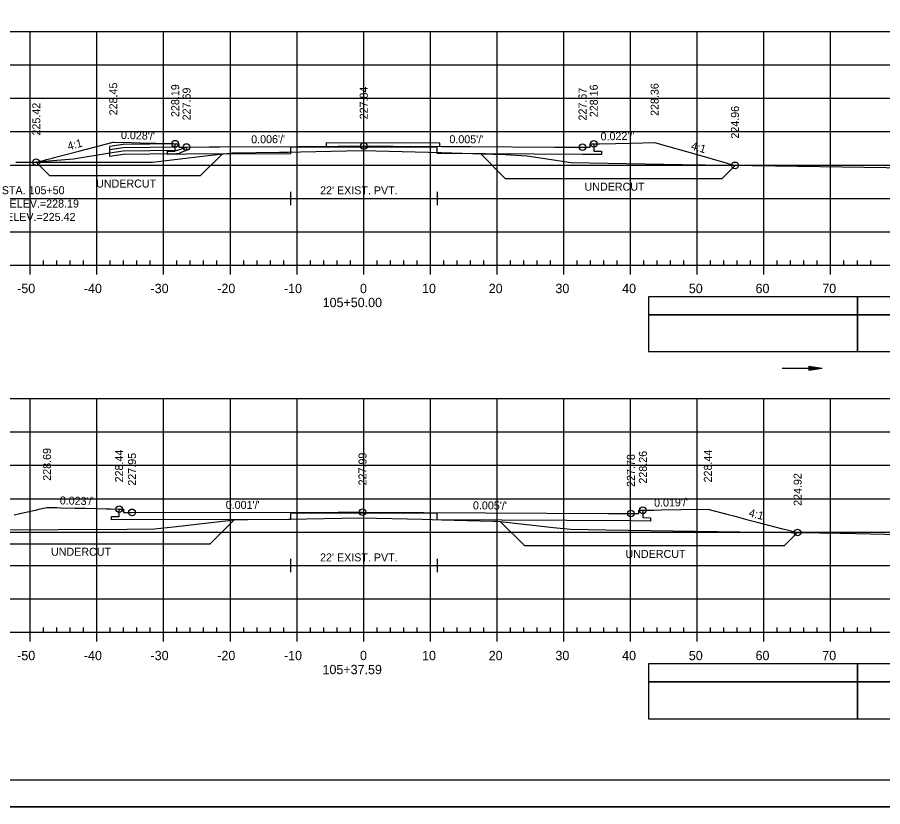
# Model space of a CAD drawing. Extents: x 1386544 to 1388153, y 379785 to 390999.
# Drawn here: x 1387880 to 1388009.8, y 380518.8 to 380637.1 of the extents above; entities that cross this region are included whole.
import ezdxf

# ---------------------------------------------------------------- set-up
doc = ezdxf.new("R2010")
doc.units = 0
for name, color, linetype in [('R_Alt Surface', 7, 'Continuous'), ('R_Axis', 7, 'Continuous'), ('R_Axis Annot', 7, 'Continuous'), ('R_Border', 7, 'Continuous'), ('R_Dimension', 7, 'Continuous'), ('R_Exist Surface', 7, 'Continuous'), ('R_Fin Surface', 7, 'Continuous'), ('R_Fin Surface Annot', 7, 'Continuous'), ('R_Grid', 7, 'Continuous'), ('R_No Plot', 7, 'Continuous'), ('R_Proposed Road', 7, 'Continuous'), ('R_Striping', 7, 'Continuous'), ('R_Water', 7, 'Continuous'), ('R_Water Annot', 7, 'Continuous')]:
    doc.layers.add(name, color=color, linetype=linetype)

msp = doc.modelspace()

# ---------------------------------------------------------------- linework, layer by layer
at = {"layer": 'R_Alt Surface'}
for points in [[(1387966.46, 380618.11), (1387966.46, 380617.01), (1387967.59, 380617), (1387967.59, 380616.5), (1387964.77, 380616.54), (1387942.97, 380616.65), (1387942.97, 380617.56), (1387931.97, 380617.62), (1387920.97, 380617.56), (1387920.97, 380616.64), (1387905.41, 380616.56), (1387902.56, 380616.54), (1387902.56, 380617.04), (1387903.7, 380617.04), (1387903.7, 380618.14)], [(1387920.97, 380610.95), (1387920.97, 380608.95)], [(1387942.97, 380610.95), (1387942.97, 380608.95)], [(1387920.97, 380609.95), (1387942.97, 380609.95)], [(1387897, 380561.81), (1387894.14, 380561.79), (1387894.14, 380562.29), (1387895.29, 380562.3), (1387895.29, 380563.39)], [(1387972.13, 380561.64), (1387942.97, 380561.8), (1387942.97, 380562.71), (1387931.97, 380562.77), (1387920.97, 380562.71), (1387920.97, 380561.79), (1387897, 380561.81)], [(1387973.82, 380563.21), (1387973.82, 380562.11), (1387974.96, 380562.1), (1387974.96, 380561.6), (1387972.13, 380561.64)], [(1387920.97, 380555.95), (1387920.97, 380553.95)], [(1387920.97, 380554.95), (1387942.97, 380554.95)], [(1387942.97, 380555.95), (1387942.97, 380553.95)]]:
    msp.add_lwpolyline(points, dxfattribs=at)
at = {"layer": 'R_Axis'}
for p, q in [((1387883.97, 380599.95), (1387883.97, 380600.65)), ((1387885.97, 380599.95), (1387885.97, 380600.65)), ((1387887.97, 380599.95), (1387887.97, 380600.65)), ((1387889.97, 380599.95), (1387889.97, 380600.65)), ((1387893.97, 380599.95), (1387893.97, 380600.65)), ((1387895.97, 380599.95), (1387895.97, 380600.65)), ((1387897.97, 380599.95), (1387897.97, 380600.65)), ((1387899.97, 380599.95), (1387899.97, 380600.65)), ((1387903.97, 380599.95), (1387903.97, 380600.65)), ((1387905.97, 380599.95), (1387905.97, 380600.65)), ((1387907.97, 380599.95), (1387907.97, 380600.65)), ((1387909.97, 380599.95), (1387909.97, 380600.65)), ((1387913.97, 380599.95), (1387913.97, 380600.65)), ((1387915.97, 380599.95), (1387915.97, 380600.65)), ((1387917.97, 380599.95), (1387917.97, 380600.65)), ((1387919.97, 380599.95), (1387919.97, 380600.65)), ((1387923.97, 380599.95), (1387923.97, 380600.65)), ((1387925.97, 380599.95), (1387925.97, 380600.65)), ((1387927.97, 380599.95), (1387927.97, 380600.65)), ((1387929.97, 380599.95), (1387929.97, 380600.65)), ((1387933.97, 380599.95), (1387933.97, 380600.65)), ((1387935.97, 380599.95), (1387935.97, 380600.65)), ((1387937.97, 380599.95), (1387937.97, 380600.65)), ((1387939.97, 380599.95), (1387939.97, 380600.65)), ((1387943.97, 380599.95), (1387943.97, 380600.65)), ((1387945.97, 380599.95), (1387945.97, 380600.65)), ((1387947.97, 380599.95), (1387947.97, 380600.65)), ((1387949.97, 380599.95), (1387949.97, 380600.65)), ((1387953.97, 380599.95), (1387953.97, 380600.65)), ((1387955.97, 380599.95), (1387955.97, 380600.65)), ((1387957.97, 380599.95), (1387957.97, 380600.65)), ((1387959.97, 380599.95), (1387959.97, 380600.65)), ((1387963.97, 380599.95), (1387963.97, 380600.65)), ((1387965.97, 380599.95), (1387965.97, 380600.65)), ((1387967.97, 380599.95), (1387967.97, 380600.65)), ((1387969.97, 380599.95), (1387969.97, 380600.65)), ((1387973.97, 380599.95), (1387973.97, 380600.65)), ((1387975.97, 380599.95), (1387975.97, 380600.65)), ((1387977.97, 380599.95), (1387977.97, 380600.65)), ((1387979.97, 380599.95), (1387979.97, 380600.65)), ((1387983.97, 380599.95), (1387983.97, 380600.65)), ((1387985.97, 380599.95), (1387985.97, 380600.65)), ((1387987.97, 380599.95), (1387987.97, 380600.65)), ((1387989.97, 380599.95), (1387989.97, 380600.65)), ((1387993.97, 380599.95), (1387993.97, 380600.65)), ((1387995.97, 380599.95), (1387995.97, 380600.65)), ((1387997.97, 380599.95), (1387997.97, 380600.65)), ((1387999.97, 380599.95), (1387999.97, 380600.65)), ((1388003.97, 380599.95), (1388003.97, 380600.65)), ((1388005.97, 380599.95), (1388005.97, 380600.65)), ((1388007.97, 380599.95), (1388007.97, 380600.65)), ((1387786.97, 380599.95), (1388076.97, 380599.95)), ((1387881.97, 380598.55), (1387881.97, 380599.95)), ((1387891.97, 380598.55), (1387891.97, 380599.95)), ((1387901.97, 380598.55), (1387901.97, 380599.95)), ((1387911.97, 380598.55), (1387911.97, 380599.95)), ((1387921.97, 380598.55), (1387921.97, 380599.95)), ((1387931.97, 380598.55), (1387931.97, 380599.95)), ((1387941.97, 380598.55), (1387941.97, 380599.95)), ((1387951.97, 380598.55), (1387951.97, 380599.95)), ((1387961.97, 380598.55), (1387961.97, 380599.95)), ((1387971.97, 380598.55), (1387971.97, 380599.95)), ((1387981.97, 380598.55), (1387981.97, 380599.95)), ((1387991.97, 380598.55), (1387991.97, 380599.95)), ((1388001.97, 380598.55), (1388001.97, 380599.95)), ((1387786.97, 380544.95), (1388076.97, 380544.95)), ((1387881.97, 380543.55), (1387881.97, 380544.95)), ((1387883.97, 380544.95), (1387883.97, 380545.65)), ((1387885.97, 380544.95), (1387885.97, 380545.65)), ((1387887.97, 380544.95), (1387887.97, 380545.65)), ((1387889.97, 380544.95), (1387889.97, 380545.65)), ((1387891.97, 380543.55), (1387891.97, 380544.95)), ((1387893.97, 380544.95), (1387893.97, 380545.65)), ((1387895.97, 380544.95), (1387895.97, 380545.65)), ((1387897.97, 380544.95), (1387897.97, 380545.65)), ((1387899.97, 380544.95), (1387899.97, 380545.65)), ((1387901.97, 380543.55), (1387901.97, 380544.95)), ((1387903.97, 380544.95), (1387903.97, 380545.65)), ((1387905.97, 380544.95), (1387905.97, 380545.65)), ((1387907.97, 380544.95), (1387907.97, 380545.65)), ((1387909.97, 380544.95), (1387909.97, 380545.65)), ((1387911.97, 380543.55), (1387911.97, 380544.95)), ((1387913.97, 380544.95), (1387913.97, 380545.65)), ((1387915.97, 380544.95), (1387915.97, 380545.65)), ((1387917.97, 380544.95), (1387917.97, 380545.65)), ((1387919.97, 380544.95), (1387919.97, 380545.65)), ((1387921.97, 380543.55), (1387921.97, 380544.95)), ((1387923.97, 380544.95), (1387923.97, 380545.65)), ((1387925.97, 380544.95), (1387925.97, 380545.65)), ((1387927.97, 380544.95), (1387927.97, 380545.65)), ((1387929.97, 380544.95), (1387929.97, 380545.65)), ((1387931.97, 380543.55), (1387931.97, 380544.95)), ((1387933.97, 380544.95), (1387933.97, 380545.65)), ((1387935.97, 380544.95), (1387935.97, 380545.65)), ((1387937.97, 380544.95), (1387937.97, 380545.65)), ((1387939.97, 380544.95), (1387939.97, 380545.65)), ((1387941.97, 380543.55), (1387941.97, 380544.95)), ((1387943.97, 380544.95), (1387943.97, 380545.65)), ((1387945.97, 380544.95), (1387945.97, 380545.65)), ((1387947.97, 380544.95), (1387947.97, 380545.65)), ((1387949.97, 380544.95), (1387949.97, 380545.65)), ((1387951.97, 380543.55), (1387951.97, 380544.95)), ((1387953.97, 380544.95), (1387953.97, 380545.65)), ((1387955.97, 380544.95), (1387955.97, 380545.65)), ((1387957.97, 380544.95), (1387957.97, 380545.65)), ((1387959.97, 380544.95), (1387959.97, 380545.65)), ((1387961.97, 380543.55), (1387961.97, 380544.95)), ((1387963.97, 380544.95), (1387963.97, 380545.65)), ((1387965.97, 380544.95), (1387965.97, 380545.65)), ((1387967.97, 380544.95), (1387967.97, 380545.65)), ((1387969.97, 380544.95), (1387969.97, 380545.65)), ((1387971.97, 380543.55), (1387971.97, 380544.95)), ((1387973.97, 380544.95), (1387973.97, 380545.65)), ((1387975.97, 380544.95), (1387975.97, 380545.65)), ((1387977.97, 380544.95), (1387977.97, 380545.65)), ((1387979.97, 380544.95), (1387979.97, 380545.65)), ((1387981.97, 380543.55), (1387981.97, 380544.95)), ((1387983.97, 380544.95), (1387983.97, 380545.65)), ((1387985.97, 380544.95), (1387985.97, 380545.65)), ((1387987.97, 380544.95), (1387987.97, 380545.65)), ((1387989.97, 380544.95), (1387989.97, 380545.65)), ((1387991.97, 380543.55), (1387991.97, 380544.95)), ((1387993.97, 380544.95), (1387993.97, 380545.65)), ((1387995.97, 380544.95), (1387995.97, 380545.65)), ((1387997.97, 380544.95), (1387997.97, 380545.65)), ((1387999.97, 380544.95), (1387999.97, 380545.65)), ((1388001.97, 380543.55), (1388001.97, 380544.95)), ((1388003.97, 380544.95), (1388003.97, 380545.65)), ((1388005.97, 380544.95), (1388005.97, 380545.65)), ((1388007.97, 380544.95), (1388007.97, 380545.65))]:
    msp.add_line(p, q, dxfattribs=at)
at = {"layer": 'R_Axis Annot'}
for points in [[(1388005.99, 380592.5), (1388076.97, 380592.5), (1388076.97, 380595.21), (1388005.99, 380595.21)], [(1388005.99, 380586.98), (1388076.97, 380586.98), (1388076.97, 380592.5), (1388005.99, 380592.5)], [(1388005.99, 380537.5), (1388076.97, 380537.5), (1388076.97, 380540.21), (1388005.99, 380540.21)], [(1388005.99, 380531.98), (1388076.97, 380531.98), (1388076.97, 380537.5), (1388005.99, 380537.5)]]:
    msp.add_lwpolyline(points, close=True, dxfattribs=at)
at = {"layer": 'R_Border'}
msp.add_line((1388090.15, 380522.78), (1387773.97, 380522.78), dxfattribs=at)
at = {"layer": 'R_Dimension'}
for p, q in [((1387910.73, 380616.59), (1387907.52, 380613.37)), ((1387949.51, 380616.61), (1387953.22, 380612.9)), ((1387882.88, 380615.37), (1387884.88, 380613.37)), ((1387987.63, 380614.9), (1387985.63, 380612.9)), ((1387912.53, 380561.78), (1387908.95, 380558.2)), ((1387952.44, 380561.54), (1387956.11, 380557.87)), ((1387997.02, 380559.87), (1387995.02, 380557.87))]:
    msp.add_line(p, q, dxfattribs=at)
for points in [[(1387884.88, 380613.37), (1387907.52, 380613.37)], [(1387985.63, 380612.9), (1387953.22, 380612.9)], [(1387869.91, 380558.2), (1387908.95, 380558.2)], [(1387995.02, 380557.87), (1387956.11, 380557.87)]]:
    msp.add_lwpolyline(points, dxfattribs=at)
at = {"layer": 'R_Exist Surface'}
for points in [[(1387879.83, 380615.37), (1387882.47, 380615.37), (1387898.82, 380615.4), (1387900.31, 380615.4), (1387905.68, 380616.03), (1387909.1, 380616.4), (1387912.27, 380616.76), (1387919.34, 380616.88), (1387920.69, 380616.89), (1387922.48, 380616.92), (1387931.67, 380617.13), (1387933.8, 380617.08), (1387943.64, 380616.81), (1387949.89, 380616.6), (1387951.32, 380616.57), (1387951.7, 380616.56), (1387952.43, 380616.55), (1387956.4, 380616.34), (1387956.46, 380616.33), (1387963.08, 380615.35), (1387979.69, 380615.03), (1387990.25, 380614.86), (1387993.72, 380614.83), (1388013.59, 380614.52)], [(1387875.73, 380560.3), (1387896.5, 380560.38), (1387900.6, 380560.42), (1387903.46, 380560.74), (1387912.53, 380561.78), (1387914.61, 380561.82), (1387920.68, 380561.89), (1387928.76, 380562.03), (1387931.64, 380562.1), (1387940.78, 380561.87), (1387943.68, 380561.79), (1387945.51, 380561.73), (1387951.39, 380561.58), (1387951.96, 380561.57), (1387952.44, 380561.54), (1387960.44, 380560.63), (1387962.98, 380560.39), (1387968.24, 380560.29), (1387991.7, 380559.92), (1388000.32, 380559.84), (1388000.7, 380559.83), (1388003.44, 380559.77), (1388014.64, 380559.52)]]:
    msp.add_lwpolyline(points, dxfattribs=at)
at = {"layer": 'R_Fin Surface'}
for points in [[(1387882.88, 380615.37), (1387884.11, 380615.68), (1387884.42, 380615.76), (1387885.32, 380615.99), (1387885.57, 380616.05), (1387889.28, 380617.03), (1387894.42, 380618.39), (1387894.57, 380618.39), (1387897.15, 380618.32), (1387898.38, 380618.28), (1387903.08, 380618.16), (1387903.4, 380618.15), (1387903.45, 380618.14), (1387903.7, 380618.14), (1387903.82, 380618.14), (1387904.27, 380618.13), (1387904.27, 380617.85), (1387904.27, 380617.63), (1387904.68, 380617.64), (1387905.41, 380617.64), (1387908.82, 380617.65), (1387910.33, 380617.66), (1387922.08, 380617.71), (1387928.15, 380617.76), (1387928.47, 380617.76), (1387931.97, 380617.79), (1387935.6, 380617.77), (1387936.38, 380617.77), (1387943.64, 380617.73), (1387944.4, 380617.72), (1387947.96, 380617.7), (1387960.64, 380617.64), (1387962.42, 380617.63), (1387964.77, 380617.62), (1387965.9, 380617.6), (1387965.9, 380617.83), (1387965.9, 380618.1), (1387966.32, 380618.11), (1387966.46, 380618.11), (1387966.83, 380618.11), (1387967.31, 380618.13), (1387972.12, 380618.23), (1387975.58, 380618.3), (1387976.09, 380618.16), (1387976.26, 380618.11), (1387981.6, 380616.6), (1387986.44, 380615.23), (1387986.57, 380615.2), (1387987.63, 380614.9)], [(1387879.55, 380562.54), (1387880.4, 380562.73), (1387882.98, 380563.3), (1387883.24, 380563.36), (1387884.48, 380563.64), (1387885.99, 380563.61), (1387886.52, 380563.6), (1387888.68, 380563.55), (1387890.2, 380563.51), (1387893.37, 380563.44), (1387894.04, 380563.42), (1387895.29, 380563.39), (1387895.65, 380563.39), (1387895.94, 380563.39), (1387895.94, 380563.21), (1387895.94, 380562.89), (1387897, 380562.89), (1387897.04, 380562.89), (1387897.23, 380562.9), (1387928.14, 380562.94), (1387931.05, 380562.94), (1387931.19, 380562.94), (1387931.22, 380562.94), (1387931.24, 380562.94), (1387931.25, 380562.94), (1387931.26, 380562.94), (1387931.26, 380562.94), (1387931.27, 380562.94), (1387931.39, 380562.94), (1387931.39, 380562.94), (1387931.46, 380562.94), (1387931.48, 380562.94), (1387931.52, 380562.94), (1387931.78, 380562.94)], [(1387931.78, 380562.94), (1387968.65, 380562.74), (1387971.84, 380562.72), (1387971.96, 380562.72), (1387971.99, 380562.72), (1387972.01, 380562.72), (1387972.01, 380562.72), (1387972.02, 380562.72), (1387972.22, 380562.72), (1387972.27, 380562.72), (1387972.96, 380562.71), (1387973.22, 380562.71), (1387973.22, 380562.85), (1387973.22, 380563.21), (1387973.58, 380563.21), (1387973.82, 380563.21), (1387975.06, 380563.23), (1387975.44, 380563.24), (1387976.6, 380563.26), (1387979.58, 380563.32), (1387983.56, 380563.39), (1387983.57, 380563.39), (1387983.58, 380563.39), (1387986.61, 380562.58), (1387987.43, 380562.36), (1387989.56, 380561.8), (1387991.16, 380561.38), (1387992.44, 380561.05), (1387994.77, 380560.44), (1387995.26, 380560.32), (1387997.02, 380559.87)]]:
    msp.add_lwpolyline(points, dxfattribs=at)
at = {"layer": 'R_Grid'}
for p, q in [((1387786.97, 380634.95), (1388076.97, 380634.95)), ((1387881.97, 380599.95), (1387881.97, 380634.95)), ((1387891.97, 380599.95), (1387891.97, 380634.95)), ((1387901.97, 380599.95), (1387901.97, 380634.95)), ((1387911.97, 380599.95), (1387911.97, 380634.95)), ((1387921.97, 380599.95), (1387921.97, 380634.95)), ((1387931.97, 380599.95), (1387931.97, 380634.95)), ((1387941.97, 380599.95), (1387941.97, 380634.95)), ((1387951.97, 380599.95), (1387951.97, 380634.95)), ((1387961.97, 380599.95), (1387961.97, 380634.95)), ((1387971.97, 380599.95), (1387971.97, 380634.95)), ((1387981.97, 380599.95), (1387981.97, 380634.95)), ((1387991.97, 380599.95), (1387991.97, 380634.95)), ((1388001.97, 380599.95), (1388001.97, 380634.95)), ((1387786.97, 380629.95), (1388076.97, 380629.95)), ((1387786.97, 380624.95), (1388076.97, 380624.95)), ((1387786.97, 380619.95), (1388076.97, 380619.95)), ((1387786.97, 380614.95), (1388076.97, 380614.95)), ((1387786.97, 380609.95), (1388076.97, 380609.95)), ((1387786.97, 380604.95), (1388076.97, 380604.95)), ((1387786.97, 380599.95), (1388076.97, 380599.95)), ((1387786.97, 380579.95), (1388076.97, 380579.95)), ((1387881.97, 380544.95), (1387881.97, 380579.95)), ((1387891.97, 380544.95), (1387891.97, 380579.95)), ((1387901.97, 380544.95), (1387901.97, 380579.95)), ((1387911.97, 380544.95), (1387911.97, 380579.95)), ((1387921.97, 380544.95), (1387921.97, 380579.95)), ((1387931.97, 380544.95), (1387931.97, 380579.95)), ((1387941.97, 380544.95), (1387941.97, 380579.95)), ((1387951.97, 380544.95), (1387951.97, 380579.95)), ((1387961.97, 380544.95), (1387961.97, 380579.95)), ((1387971.97, 380544.95), (1387971.97, 380579.95)), ((1387981.97, 380544.95), (1387981.97, 380579.95)), ((1387991.97, 380544.95), (1387991.97, 380579.95)), ((1388001.97, 380544.95), (1388001.97, 380579.95)), ((1387786.97, 380574.95), (1388076.97, 380574.95)), ((1387786.97, 380569.95), (1388076.97, 380569.95)), ((1387786.97, 380564.95), (1388076.97, 380564.95)), ((1387786.97, 380559.95), (1388076.97, 380559.95)), ((1387786.97, 380554.95), (1388076.97, 380554.95)), ((1387786.97, 380549.95), (1388076.97, 380549.95)), ((1387786.97, 380544.95), (1388076.97, 380544.95))]:
    msp.add_line(p, q, dxfattribs=at)
at = {"layer": 'R_No Plot'}
msp.add_line((1387761.57, 380518.8), (1388094.9, 380518.8), dxfattribs=at)
for points in [[(1387761.56, 380732.14), (1388094.9, 380732.14), (1388094.9, 380518.8), (1387761.56, 380518.8)], [(1388007.89, 380728.24), (1388027.51, 380728.24), (1388027.51, 380718.36), (1388043.62, 380718.36), (1388066.82, 380718.36), (1388066.82, 380694.03), (1388090.15, 380694.03), (1388090.15, 380522.78), (1387773.97, 380522.78), (1387773.97, 380728.24)]]:
    msp.add_lwpolyline(points, close=True, dxfattribs=at)
for centre in [(1387903.7, 380618.14), (1387966.46, 380618.11), (1387905.41, 380617.64), (1387931.97, 380617.79), (1387964.77, 380617.62), (1387882.88, 380615.37), (1387987.63, 380614.9), (1387895.29, 380563.39), (1387897.23, 380562.9), (1387931.78, 380562.94), (1387931.78, 380562.94), (1387972.02, 380562.72), (1387973.82, 380563.21), (1387997.02, 380559.87)]:
    msp.add_circle(centre, 0.5, dxfattribs=at)
at = {"layer": 'R_Proposed Road'}
for p, q in [((1387926.41, 380617.75), (1387926.41, 380618.25)), ((1387943.37, 380618.23), (1387926.41, 380618.25)), ((1387943.37, 380617.73), (1387943.37, 380618.23))]:
    msp.add_line(p, q, dxfattribs=at)
at = {"layer": 'R_Striping'}
for points in [[(1387974.65, 380592.51), (1388005.99, 380592.51), (1388005.99, 380595.21), (1387974.65, 380595.21)], [(1387974.65, 380586.98), (1388005.99, 380586.98), (1388005.99, 380592.51), (1387974.65, 380592.51)], [(1387974.65, 380537.51), (1388005.99, 380537.51), (1388005.99, 380540.21), (1387974.65, 380540.21)], [(1387974.65, 380531.98), (1388005.99, 380531.98), (1388005.99, 380537.51), (1387974.65, 380537.51)]]:
    msp.add_lwpolyline(points, close=True, dxfattribs=at)
at = {"layer": 'R_Water'}
for p, q in [((1387895.91, 380618.04), (1387893.91, 380617.71)), ((1387893.91, 380616.21), (1387893.91, 380617.71)), ((1387895.91, 380617.54), (1387893.91, 380617.21)), ((1387903.91, 380618.12), (1387895.91, 380618.04)), ((1387903.91, 380617.62), (1387895.91, 380617.54)), ((1387893.91, 380616.71), (1387888.48, 380615.8)), ((1387895.91, 380617.04), (1387893.91, 380616.71)), ((1387895.91, 380616.54), (1387893.91, 380616.21)), ((1387903.91, 380617.12), (1387895.91, 380617.04)), ((1387903.91, 380616.62), (1387895.91, 380616.54)), ((1387998.72, 380584.83), (1388000.72, 380584.53)), ((1387998.72, 380584.83), (1387998.72, 380584.23)), ((1387998.72, 380584.83), (1388000.72, 380584.53)), ((1387998.72, 380584.83), (1387998.72, 380584.23)), ((1387998.72, 380584.78), (1388000.39, 380584.53)), ((1387998.72, 380584.78), (1388000.39, 380584.53)), ((1387998.72, 380584.73), (1388000.05, 380584.53)), ((1387998.72, 380584.73), (1388000.05, 380584.53)), ((1387994.72, 380584.53), (1388000.72, 380584.53)), ((1387998.72, 380584.68), (1387999.71, 380584.53)), ((1387998.72, 380584.68), (1387999.71, 380584.53)), ((1387998.72, 380584.63), (1387999.37, 380584.53)), ((1387998.72, 380584.63), (1387999.37, 380584.53)), ((1387998.72, 380584.58), (1387999.04, 380584.53)), ((1387998.72, 380584.58), (1387999.04, 380584.53)), ((1387998.72, 380584.23), (1388000.72, 380584.53)), ((1387998.72, 380584.44), (1387999.37, 380584.53)), ((1387998.72, 380584.34), (1388000.05, 380584.53)), ((1387998.72, 380584.28), (1388000.39, 380584.53)), ((1387998.72, 380584.39), (1387999.71, 380584.53)), ((1387998.72, 380584.49), (1387999.04, 380584.53)), ((1387998.72, 380584.23), (1388000.72, 380584.53)), ((1387998.72, 380584.44), (1387999.37, 380584.53)), ((1387998.72, 380584.34), (1388000.05, 380584.53)), ((1387998.72, 380584.28), (1388000.39, 380584.53)), ((1387998.72, 380584.39), (1387999.71, 380584.53)), ((1387998.72, 380584.49), (1387999.04, 380584.53))]:
    msp.add_line(p, q, dxfattribs=at)
for points in [[(1387903.91, 380618.12), (1387904.16, 380618.12), (1387904.24, 380617.96), (1387903.91, 380617.62)], [(1387903.91, 380617.12), (1387905.41, 380617.64), (1387905.41, 380617.11), (1387904.41, 380616.77), (1387904.41, 380616.62), (1387903.91, 380616.62)], [(1387888.48, 380615.8), (1387888.48, 380615.8), (1387882.88, 380615.37)]]:
    msp.add_lwpolyline(points, dxfattribs=at)

# ---------------------------------------------------------------- texts
at = {"layer": 'R_Axis Annot'}
for s, p in [('-50', (1387880.01, 380595.75)), ('-40', (1387890.01, 380595.75)), ('-30', (1387900.01, 380595.75)), ('-20', (1387910.01, 380595.75)), ('-10', (1387920.01, 380595.75)), ('0', (1387931.41, 380595.75)), ('10', (1387940.71, 380595.75)), ('20', (1387950.71, 380595.75)), ('30', (1387960.71, 380595.75)), ('40', (1387970.71, 380595.75)), ('50', (1387980.71, 380595.75)), ('60', (1387990.71, 380595.75)), ('70', (1388000.71, 380595.75)), ('105+50.00', (1387925.81, 380593.65)), ('-50', (1387880.01, 380540.75)), ('-40', (1387890.01, 380540.75)), ('-30', (1387900.01, 380540.75)), ('-20', (1387910.01, 380540.75)), ('-10', (1387920.01, 380540.75)), ('0', (1387931.41, 380540.75)), ('10', (1387940.71, 380540.75)), ('20', (1387950.71, 380540.75)), ('30', (1387960.71, 380540.75)), ('40', (1387970.71, 380540.75)), ('50', (1387980.71, 380540.75)), ('60', (1387990.71, 380540.75)), ('70', (1388000.71, 380540.75)), ('105+37.59', (1387925.79, 380538.65))]:
    msp.add_text(s, height=1.4, dxfattribs=at).set_placement(p)
at = {"layer": 'R_Dimension'}
for p in [(1387891.85, 380611.57), (1387965.07, 380611.1), (1387885.08, 380556.4), (1387971.21, 380556.07)]:
    msp.add_text('UNDERCUT', height=1.2, dxfattribs=at).set_placement(p)
at = {"layer": 'R_Fin Surface Annot'}
for s, rotation, p in [('228.45', 90, (1387895.02, 380622.39)), ('228.19', 90, (1387904.3, 380622.14)), ('227.69', 90, (1387906.01, 380621.64)), ('227.84', 90, (1387932.57, 380621.79)), ('227.67', 90, (1387965.37, 380621.62)), ('228.16', 90, (1387967.06, 380622.11)), ('228.36', 90, (1387976.18, 380622.3)), ('225.42', 90, (1387883.48, 380619.37)), ('224.96', 90, (1387988.23, 380618.9)), ("0.028'/'", 358.4241, (1387895.56, 380618.86)), ("0.022'/'", 1.2408, (1387967.49, 380618.63)), ('4:1', 14.6681, (1387887.72, 380617.16)), ("0.006'/'", 0.3208, (1387915.1, 380618.2)), ("0.005'/'", 359.7021, (1387944.81, 380618.22)), ('4:1', 344.2435, (1387980.94, 380617.31)), ('228.69', 90, (1387885.08, 380567.64)), ('228.44', 90, (1387895.89, 380567.39)), ('227.95', 90, (1387897.83, 380566.9)), ('227.99', 90, (1387932.38, 380566.94)), ('228.26', 90, (1387974.42, 380567.21)), ('228.44', 90, (1387984.16, 380567.39)), ('227.78', 90, (1387972.62, 380566.72)), ('224.92', 90, (1387997.62, 380563.87)), ("0.023'/'", 358.6783, (1387886.39, 380564.1)), ("0.001'/'", 0.0731, (1387911.28, 380563.41)), ("0.005'/'", 359.6905, (1387948.34, 380563.35)), ("0.019'/'", 1.0818, (1387975.51, 380563.74)), ('4:1', 345.3288, (1387989.61, 380562.32))]:
    msp.add_text(s, height=1.2, rotation=rotation, dxfattribs=at).set_placement(p)
at = {"layer": 'R_No Plot'}
for p in [(1387894.38, 380618.34), (1387975.53, 380618.25), (1387884.44, 380563.59), (1387983.52, 380563.34)]:
    msp.add_text('+', height=0.1, dxfattribs=at).set_placement(p)
at = {"layer": 'R_Water'}
for p in [(1387925.42, 380610.55), (1387925.42, 380555.55)]:
    msp.add_text("22' EXIST. PVT.", height=1.2, dxfattribs=at).set_placement(p)
at = {"layer": 'R_Water Annot'}
for s, p in [('STA. 105+50', (1387877.71, 380610.57)), ('TOP ELEV.=228.19', (1387875.13, 380608.57)), ('F.L. ELEV.=225.42', (1387875.15, 380606.57))]:
    msp.add_text(s, height=1.2, dxfattribs=at).set_placement(p)

doc.saveas('drawing.dxf')
